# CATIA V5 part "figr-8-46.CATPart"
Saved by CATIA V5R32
Part number: Part1
Bounding box of the stored display mesh (mm): x -46.99 to 46.99, y -111.421 to 111.421, z 0 to 30
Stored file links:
  D:\PROJECTS\Project 2022\CATIA V5 6R 2022\Resources\Part Files\c08_catia_v5_6r2022_prt\figr-8-46.CATPart
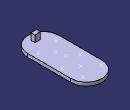
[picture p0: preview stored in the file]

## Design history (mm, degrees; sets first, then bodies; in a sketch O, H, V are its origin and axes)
Set1
  Point1: type OnPlane, Support end face of Pad1, H -29.651, V 16.503, Direction (1, 0, 0)
  Point2: type OnPlane, Support end face of Pad1, H 32.527, V 24.633, Direction (1, 0, 0)
  Point3: type OnPlane, Support end face of Pad1, H -0.958, V 47.624, Direction (1, 0, 0)
  Point4: type OnPlane, Support end face of Pad1, H -32.979, V 77.546, Direction (1, 0, 0)
  Point5: type OnPlane, Support end face of Pad1, H -4.198, V -0.555, Direction (1, 0, 0)
  Point6: type OnPlane, Support end face of Pad1, H 24.642, V 78.69, Direction (1, 0, 0)
  Point7: type OnPlane, Support end face of Pad1, H 1.401, V -27.141, Direction (1, 0, 0)
  Point8: type OnPlane, Support end face of Pad1, H -28.672, V -54.785, Direction (1, 0, 0)
  Point9: type OnPlane, Support end face of Pad1, H 29.834, V -50.327, Direction (1, 0, 0)
Body1 (main body)
  Sketch1 on xy-plane, origin (0, 0, 0), H (1, 0, 0), V (0, 1, 0)
    construction line L1 (-46.9897, 64.4313) -> (46.9897, 64.4313)
    line L2 (46.9897, 64.4313) -> (46.9897, -64.4313)
    construction line L3 (46.9897, -64.4313) -> (-46.9897, -64.4313)
    line L4 (-46.9897, -64.4313) -> (-46.9897, 64.4313)
    axis line L5 (46.9897, -64.4313) -> (-46.9897, 64.4313)
    arc A1 centre (0, 64.4313) radius 46.9897 from (-46.9897, 64.4313) to (46.9897, 64.4313) cw
    arc A2 centre (0, -64.4313) radius 46.9897 from (-46.9897, -64.4313) to (46.9897, -64.4313) ccw
    point P7 (0, -111.4211)
    length L3 = 93.9795
    length L2 = 128.8627
    horizontal: L1 H, L3 H
    vertical: L2 V, L4 V
    midpoint: O L5
    tangency: A1 L2, A2 L4
    coincidence: A2 P7, P7 V
  Pad1: profile Sketch1, direction (0, 0, 1), length 10
  Sketch2 on face of Pad1, origin (0, 0, 10), H (1, 0, 0), V (0, 1, 0)
    line L1 (-8.4317, -82.0722) -> (8.3047, -82.0722)
    line L2 (8.3047, -82.0722) -> (8.3047, -93.8638)
    line L3 (8.3047, -93.8638) -> (-8.4317, -93.8638)
    line L4 (-8.4317, -93.8638) -> (-8.4317, -82.0722)
    horizontal: L1 H, L3 H
    vertical: L2 V, L4 V
  Pad2: profile Sketch2, direction (0, 0, 1), length 20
